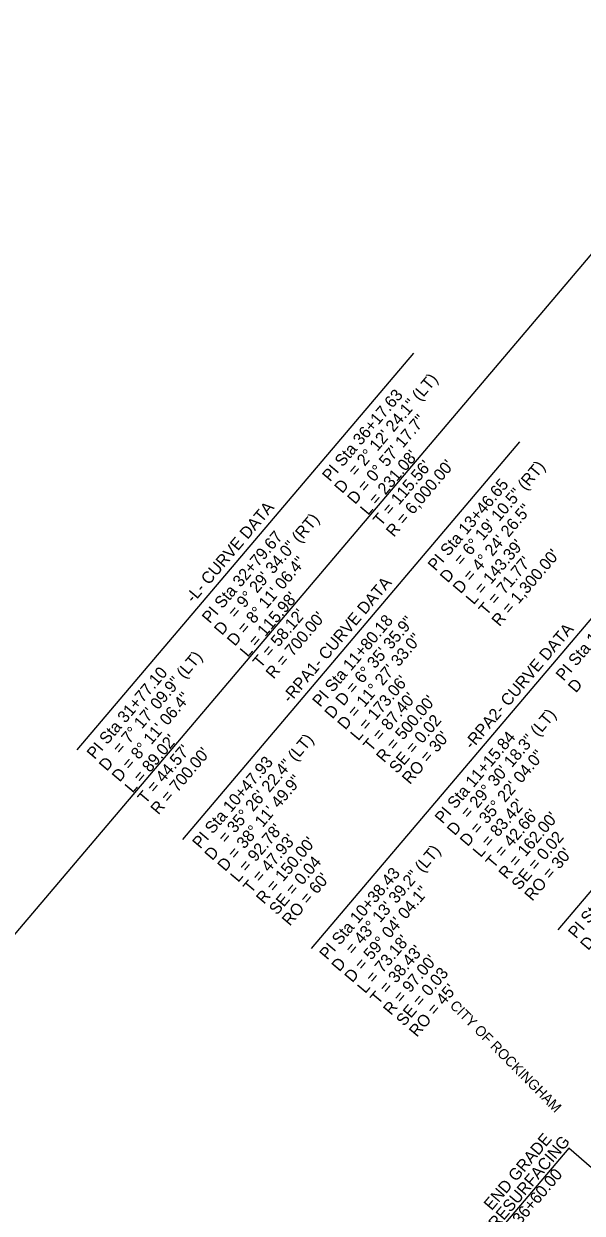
# Model space of a CAD drawing. Extents: x 1761082 to 1764358, y 421907 to 425434.
# Drawn here: x 1762548 to 1762878, y 424026 to 424730 of the extents above; entities that cross this region are included whole.
import ezdxf

# ---------------------------------------------------------------- set-up
doc = ezdxf.new("R2010")
doc.units = 0
for name, color, linetype in [('MARK UTURN ARROW CELL', 7, 'Continuous'), ('Prop Mkg Solid White Multiple Diagonals V8i', 7, 'Continuous'), ('Prop Mkg Solid Yel Skip LT', 7, 'Continuous'), ('Prop Mkr Yel 40ft Spc', 7, 'Continuous')]:
    doc.layers.add(name, color=color, linetype=linetype)

msp = doc.modelspace()

# ---------------------------------------------------------------- linework, layer by layer
at = {"layer": 'MARK UTURN ARROW CELL'}
for p, q in [((1762579.19, 424300.23), (1762778.24, 424535.2)), ((1762863.58, 424193.79), (1763141.97, 424522.4)), ((1762717.84, 424182.78), (1762982.36, 424495.02)), ((1762641.63, 424247.34), (1762841, 424482.67))]:
    msp.add_line(p, q, dxfattribs=at)
msp.add_lwpolyline([(1763013.15, 423940.16), (1762869.88, 424064.58), (1762781.79, 423960.6)], dxfattribs=at)
at = {"layer": 'Prop Mkg Solid White Multiple Diagonals V8i'}
msp.add_line((1761203.63, 422611.03), (1763595.27, 425434.16), dxfattribs=at)

# ---------------------------------------------------------------- texts
at = {"layer": 'MARK UTURN ARROW CELL'}
for s, p in [('END GRADE', (1762824.33, 424027.23)), ('BEGIN MILLING/RESURFACING', (1762780.64, 423961.47)), ('-L- POC Sta.  36+60.00', (1762803.22, 423973.93))]:
    msp.add_text(s, height=7, rotation=49.7301, dxfattribs=at).set_placement(p)
at = {"layer": 'Prop Mkg Solid Yel Skip LT'}
msp.add_text('CITY OF ROCKINGHAM', height=6, rotation=314.7355, dxfattribs=at).set_placement((1762799.19, 424148.47))
at = {"layer": 'Prop Mkr Yel 40ft Spc'}
for s, rotation, p in [('= 2%%d 12\' 24.1" (LT)', 49.7585, (1762744.04, 424461.67)), ('PI Sta 36+17.63', 49.7585, (1762728.77, 424458.64)), ('D = 0%%d 57\' 17.7"', 49.7585, (1762743.6, 424445.21)), ("L = 231.08'", 49.7585, (1762751.24, 424438.75)), ("T = 115.56'", 49.7585, (1762758.87, 424432.29)), ("R = 6,000.00'", 49.7585, (1762766.5, 424425.83)), ('= 6%%d 19\' 10.5" (RT)', 49.74724, (1762806.49, 424408.77)), ('PI Sta 13+46.65', 49.74724, (1762791.21, 424405.74)), ('D', 49.7585, (1762735.97, 424451.67)), ('-L- CURVE DATA', 49.7301, (1762648.01, 424386.81)), ('= 9%%d 29\' 34.0" (RT)', 49.7273, (1762672.92, 424377.7)), ('D = 4%%d 24\' 26.5"', 49.74724, (1762806.04, 424392.31)), ('PI Sta 32+79.67', 49.7273, (1762657.65, 424374.69)), ("L = 143.39'", 49.74724, (1762813.67, 424385.84)), ("R = 1,300.00'", 49.74724, (1762828.94, 424372.92)), ('D = 8%%d 11\' 06.4"', 49.7273, (1762672.47, 424361.25)), ("T = 71.77'", 49.74724, (1762821.31, 424379.38)), ('D', 49.74724, (1762798.41, 424398.77)), ('-RPA1- CURVE DATA', 49.7301, (1762705.09, 424327.58)), ("L = 115.98'", 49.7273, (1762680.1, 424354.78)), ('PI Sta 12+48.11', 49.83368, (1762866.92, 424340.6)), ("T = 58.12'", 49.7273, (1762687.73, 424348.32)), ("R = 700.00'", 49.7273, (1762695.36, 424341.85)), ('PI Sta 11+80.18', 49.78888, (1762722.95, 424325.17)), ('D = 6%%d 35\' 35.9"', 49.78888, (1762736.61, 424325.84)), ('D', 49.7273, (1762664.84, 424367.71)), ('D = 11%%d 27\' 33.0"', 49.78888, (1762737.79, 424311.74)), ('-RPA2- CURVE DATA', 49.7301, (1762812.73, 424300.13)), ('= 7%%d 17\' 09.9" (LT)', 49.76602, (1762604.8, 424297.31)), ('PI Sta 31+77.10', 49.76602, (1762589.53, 424294.28)), ("L = 173.06'", 49.78888, (1762745.43, 424305.29)), ('D', 49.83368, (1762874.13, 424333.64)), ('D = 8%%d 11\' 06.4"', 49.76602, (1762604.36, 424280.85)), ("T = 87.40'", 49.78888, (1762753.07, 424298.83)), ("R = 500.00'", 49.78888, (1762760.7, 424292.38)), ('D', 49.78888, (1762730.16, 424318.2)), ('SE = 0.02', 49.78888, (1762768.33, 424285.91)), ('= 29%%d 30\' 18.3" (LT)', 49.75378, (1762810.63, 424259.15)), ("L = 89.02'", 49.76602, (1762611.99, 424274.39)), ('= 35%%d 26\' 22.4" (LT)', 49.75098, (1762667.24, 424244.4)), ("RO = 30'", 49.78888, (1762775.96, 424279.45)), ('PI Sta 11+15.84', 49.75378, (1762795.36, 424256.12)), ("T = 44.57'", 49.76602, (1762619.63, 424267.93)), ("R = 700.00'", 49.76602, (1762627.26, 424261.47)), ('D = 35%%d 22\' 04.0"', 49.75378, (1762810.19, 424242.69)), ('D', 49.76602, (1762596.73, 424287.3)), ('PI Sta 10+47.93', 49.75098, (1762651.97, 424241.38)), ('D = 38%%d 11\' 49.9"', 49.75098, (1762666.8, 424227.94)), ("L = 83.42'", 49.75378, (1762817.82, 424236.23)), ("T = 42.66'", 49.75378, (1762825.45, 424229.77)), ("R = 162.00'", 49.75378, (1762833.08, 424223.31)), ("L = 92.78'", 49.75098, (1762674.43, 424221.48)), ('D', 49.75378, (1762802.55, 424249.15)), ("T = 47.93'", 49.75098, (1762682.06, 424215.02)), ('SE = 0.02', 49.75378, (1762840.71, 424216.84)), ('D', 49.75098, (1762659.17, 424234.4)), ("R = 150.00'", 49.75098, (1762689.7, 424208.56)), ('= 43%%d 13\' 39.2" (LT)', 49.79927, (1762742.37, 424178.58)), ("RO = 30'", 49.75378, (1762848.34, 424210.38)), ('PI Sta 10+88.46', 49.76906, (1762874.21, 424188.17)), ('SE = 0.04', 49.75098, (1762697.33, 424202.1)), ('PI Sta 10+38.43', 49.79927, (1762727.1, 424175.55)), ("RO = 60'", 49.75098, (1762704.96, 424195.63)), ('D = 59%%d 04\' 04.1"', 49.79927, (1762741.94, 424162.13)), ("L = 73.18'", 49.79927, (1762749.57, 424155.67)), ('D', 49.76906, (1762881.41, 424181.2)), ("T = 38.43'", 49.79927, (1762757.21, 424149.22)), ("R = 97.00'", 49.79927, (1762764.85, 424142.76)), ('D', 49.79927, (1762734.3, 424168.58)), ('SE = 0.03', 49.79927, (1762772.48, 424136.3)), ("RO = 45'", 49.79927, (1762780.11, 424129.83))]:
    msp.add_text(s, height=7, rotation=rotation, dxfattribs=at).set_placement(p)

doc.saveas('drawing.dxf')
